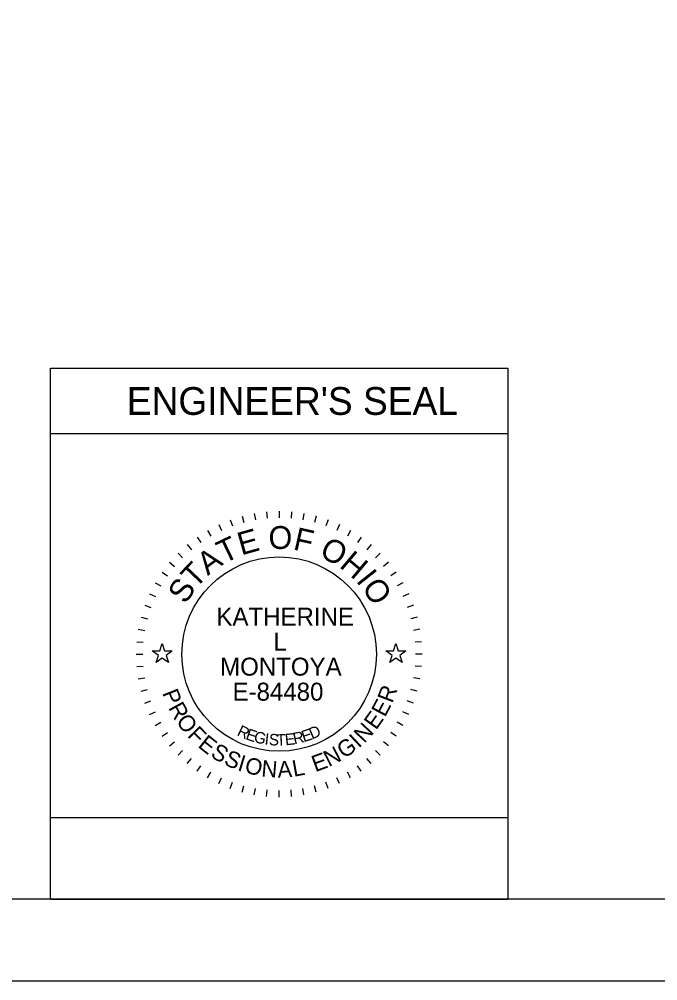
# Model space of a CAD drawing. Extents: x -12 to 164, y -741 to 24.
# Drawn here: x 21.41 to 25.32, y 0 to 5.89 of the extents above; entities that cross this region are included whole.
import ezdxf

# ---------------------------------------------------------------- set-up
doc = ezdxf.new("R2010")
doc.units = 0
for name, color, linetype in [('PM_P_CL_Dashed', 7, 'Continuous'), ('SH_Border', 7, 'Continuous'), ('SH_Cut_Line', 7, 'Continuous'), ('SH_Data', 7, 'Continuous')]:
    doc.layers.add(name, color=color, linetype=linetype)

msp = doc.modelspace()

# ---------------------------------------------------------------- linework, layer by layer
at = {"layer": 'PM_P_CL_Dashed'}
for p, q in [((22.7785, 2.8452), (22.7889, 2.8065)), ((22.8531, 2.8617), (22.86, 2.8223)), ((22.9287, 2.8717), (22.9322, 2.8318)), ((23.005, 2.875), (23.005, 2.835)), ((23.0813, 2.8717), (23.0778, 2.8318)), ((23.1569, 2.8617), (23.15, 2.8223)), ((23.2315, 2.8452), (23.2211, 2.8065)), ((22.6352, 2.793), (22.6521, 2.7568)), ((22.7057, 2.8222), (22.7194, 2.7846)), ((23.3043, 2.8222), (23.2906, 2.7846)), ((23.3748, 2.793), (23.3579, 2.7568)), ((22.5031, 2.7168), (22.5261, 2.684)), ((22.5675, 2.7578), (22.5875, 2.7231)), ((23.4425, 2.7578), (23.4225, 2.7231)), ((23.5069, 2.7168), (23.4839, 2.684)), ((22.4426, 2.6703), (22.4683, 2.6396)), ((23.5674, 2.6703), (23.5417, 2.6396)), ((22.3863, 2.6187), (22.4146, 2.5904)), ((23.6237, 2.6187), (23.5954, 2.5904)), ((22.3347, 2.5624), (22.3654, 2.5367)), ((23.6753, 2.5624), (23.6446, 2.5367)), ((22.2882, 2.5019), (22.321, 2.4789)), ((23.7218, 2.5019), (23.689, 2.4789)), ((22.2472, 2.4375), (22.2819, 2.4175)), ((23.7628, 2.4375), (23.7281, 2.4175)), ((22.212, 2.3698), (22.2482, 2.3529)), ((23.798, 2.3698), (23.7618, 2.3529)), ((22.1828, 2.2993), (22.2204, 2.2856)), ((23.8272, 2.2993), (23.7896, 2.2856)), ((22.1598, 2.2265), (22.1985, 2.2161)), ((23.8502, 2.2265), (23.8115, 2.2161)), ((22.1433, 2.1519), (22.1827, 2.145)), ((23.8667, 2.1519), (23.8273, 2.145)), ((22.1333, 2.0763), (22.1732, 2.0728)), ((23.8767, 2.0763), (23.8368, 2.0728)), ((22.13, 2), (22.17, 2)), ((23.88, 2), (23.84, 2)), ((22.1333, 1.9237), (22.1732, 1.9272)), ((23.8767, 1.9237), (23.8368, 1.9272)), ((22.1433, 1.8481), (22.1827, 1.855)), ((23.8667, 1.8481), (23.8273, 1.855)), ((22.1598, 1.7735), (22.1985, 1.7839)), ((23.8502, 1.7735), (23.8115, 1.7839)), ((22.1828, 1.7007), (22.2204, 1.7144)), ((23.8272, 1.7007), (23.7896, 1.7144)), ((22.212, 1.6302), (22.2482, 1.6471)), ((23.798, 1.6302), (23.7618, 1.6471)), ((22.2472, 1.5625), (22.2819, 1.5825)), ((23.7628, 1.5625), (23.7281, 1.5825)), ((22.2882, 1.4981), (22.321, 1.5211)), ((23.7218, 1.4981), (23.689, 1.5211)), ((22.3347, 1.4376), (22.3654, 1.4633)), ((23.6753, 1.4376), (23.6446, 1.4633)), ((22.3863, 1.3813), (22.4146, 1.4096)), ((22.4426, 1.3297), (22.4683, 1.3604)), ((23.5674, 1.3297), (23.5417, 1.3604)), ((23.6237, 1.3813), (23.5954, 1.4096)), ((22.5031, 1.2832), (22.5261, 1.316)), ((23.5069, 1.2832), (23.4839, 1.316)), ((22.5675, 1.2422), (22.5875, 1.2769)), ((22.6352, 1.207), (22.6521, 1.2432)), ((23.3748, 1.207), (23.3579, 1.2432)), ((23.4425, 1.2422), (23.4225, 1.2769)), ((22.7057, 1.1778), (22.7194, 1.2154)), ((22.7785, 1.1548), (22.7889, 1.1935)), ((22.8531, 1.1383), (22.86, 1.1777)), ((23.1569, 1.1383), (23.15, 1.1777)), ((23.2315, 1.1548), (23.2211, 1.1935)), ((23.3043, 1.1778), (23.2906, 1.2154)), ((22.9287, 1.1283), (22.9322, 1.1682)), ((23.005, 1.125), (23.005, 1.165)), ((23.0813, 1.1283), (23.0778, 1.1682))]:
    msp.add_line(p, q, dxfattribs=at)
for points in [[(22.2286, 2.02), (22.2755, 2.02), (22.29, 2.0645), (22.3045, 2.02), (22.3514, 2.02), (22.3135, 1.9924), (22.328, 1.9478), (22.29, 1.9754), (22.252, 1.9478), (22.2665, 1.9924)], [(23.6586, 2.02), (23.7055, 2.02), (23.72, 2.0645), (23.7345, 2.02), (23.7814, 2.02), (23.7435, 1.9924), (23.758, 1.9478), (23.72, 1.9754), (23.682, 1.9478), (23.6965, 1.9924)]]:
    msp.add_lwpolyline(points, close=True, dxfattribs=at)
msp.add_circle((23.005, 2), 0.595, dxfattribs=at)
at = {"layer": 'SH_Border'}
msp.add_lwpolyline([(1.5, 21.5), (33.5, 21.5), (33.5, 0.5), (1.5, 0.5)], close=True, dxfattribs=at)
at = {"layer": 'SH_Cut_Line'}
msp.add_lwpolyline([(0, 0), (34, 0), (34, 22), (0, 22)], close=True, dxfattribs=at)
at = {"layer": 'SH_Data'}
for p, q in [((21.605, 0.5), (21.605, 3.75)), ((21.605, 3.75), (24.405, 3.75)), ((24.405, 3.75), (24.405, 0.5)), ((21.605, 3.35), (24.405, 3.35)), ((21.605, 0.5), (24.405, 0.5))]:
    msp.add_line(p, q, dxfattribs=at)
msp.add_lwpolyline([(21.605, 0.5), (21.605, 1), (24.405, 1), (24.405, 0.5)], close=True, dxfattribs=at)

# ---------------------------------------------------------------- texts
at = {"layer": 'PM_P_CL_Dashed'}
for s, height, rotation, p in [('E', 0.14, 15.75706, (22.7734, 2.6038)), ('O', 0.14, 359.78119, (22.9397, 2.6443)), ('F', 0.14, 347.43619, (23.0861, 2.6417)), ('T', 0.14, 25.71674, (22.6666, 2.5518)), ('O', 0.14, 332.25863, (23.2448, 2.6015)), ('A', 0.14, 36.47472, (22.5684, 2.4781)), ('H', 0.14, 319.91363, (23.3682, 2.5361)), ('T', 0.14, 46.4344, (22.4933, 2.3964)), ('I', 0.14, 308.36695, (23.4715, 2.4483)), ('S', 0.14, 57.19238, (22.4331, 2.3014)), ('O', 0.14, 303.14906, (23.5071, 2.4089)), ('P', 0.1, 291.49398, (22.2873, 1.7621)), ('R', 0.1, 69.23216, (23.6969, 1.6954)), ('R', 0.1, 298.73106, (22.324, 1.6717)), ('E', 0.1, 61.99508, (23.6526, 1.6098)), ('E', 0.1, 54.75801, (23.5983, 1.5314)), ('O', 0.1, 306.46664, (22.3705, 1.5883)), ('F', 0.1, 314.7068, (22.4393, 1.4983)), ('R', 0.07, 334.48695, (22.7425, 1.5051)), ('E', 0.07, 341.03996, (22.7956, 1.4801)), ('E', 0.07, 17.68363, (23.1548, 1.4602)), ('D', 0.07, 23.30524, (23.206, 1.477)), ('N', 0.1, 47.02243, (23.5252, 1.4508)), ('E', 0.1, 321.43929, (22.5028, 1.4348)), ('G', 0.07, 347.47515, (22.8464, 1.4618)), ('I', 0.07, 353.78581, (22.9141, 1.4468)), ('S', 0.07, 356.89262, (22.9408, 1.4429)), ('T', 0.07, 3.00609, (22.9907, 1.4387)), ('E', 0.07, 6.01169, (23.0439, 1.4412)), ('R', 0.07, 11.91844, (23.0975, 1.4474)), ('G', 0.1, 35.04687, (23.4031, 1.357)), ('I', 0.1, 43.28703, (23.4918, 1.4214)), ('S', 0.1, 328.67637, (22.5793, 1.3752)), ('N', 0.1, 27.31129, (23.3095, 1.3075)), ('S', 0.1, 335.91345, (22.6614, 1.3266)), ('I', 0.1, 343.15053, (22.7456, 1.2897)), ('O', 0.1, 346.88592, (22.7889, 1.2751)), ('E', 0.1, 20.07421, (23.2262, 1.277)), ('N', 0.1, 355.12608, (22.8938, 1.2517)), ('A', 0.1, 2.86166, (22.9973, 1.2437)), ('L', 0.1, 10.09874, (23.0944, 1.249))]:
    msp.add_text(s, height=height, rotation=rotation, dxfattribs=at).set_placement(p)
for s, p in [('KATHERINE', (22.6213, 2.1749)), ('L', (22.9695, 2.0216)), ('MONTOYA', (22.644, 1.8684)), ('E-84480', (22.7199, 1.7151))]:
    msp.add_text(s, height=0.11, dxfattribs=at).set_placement(p)
at = {"layer": 'SH_Data'}
msp.add_text("ENGINEER'S SEAL", height=0.17, dxfattribs=at).set_placement((22.0726, 3.465))

doc.saveas('drawing.dxf')
